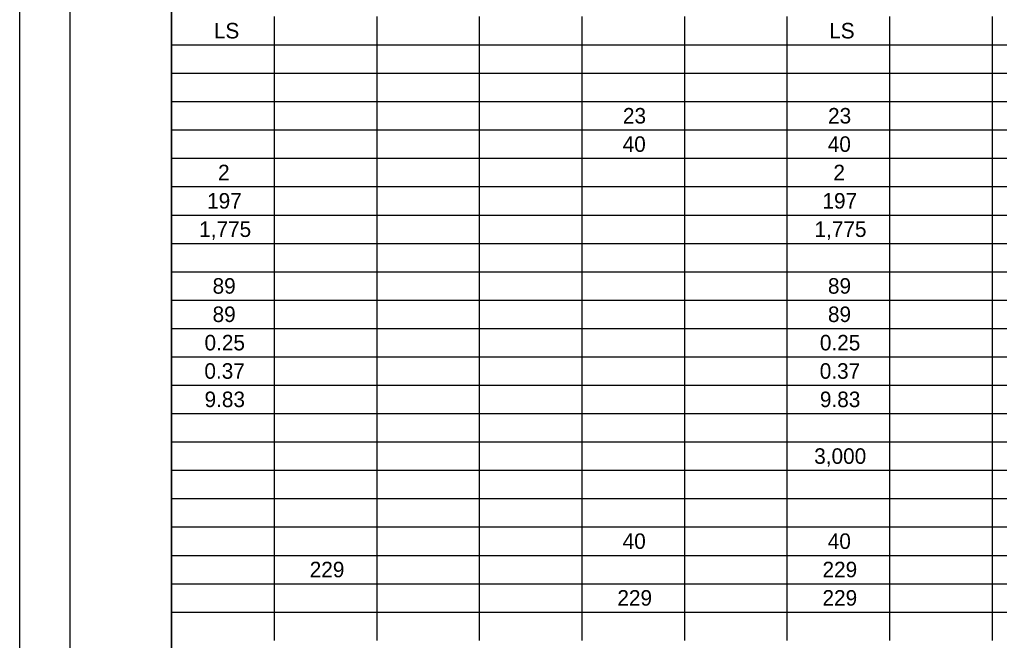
# Model space of a CAD drawing. Extents: x 0 to 34, y 0 to 22.
# Drawn here: x 0 to 9.67, y 9.74 to 15.87 of the extents above; entities that cross this region are included whole.
import ezdxf

# ---------------------------------------------------------------- set-up
doc = ezdxf.new("R2010")
doc.units = 0
for name, color, linetype in [('SH_Border', 7, 'Continuous'), ('SH_Cut_Line', 7, 'Continuous'), ('SH_Text', 7, 'Continuous')]:
    doc.layers.add(name, color=color, linetype=linetype)

msp = doc.modelspace()

# ---------------------------------------------------------------- linework, layer by layer
at = {"layer": 'SH_Border'}
for points in [[(0.5, 21.5), (1.5, 21.5), (1.5, 0.5), (0.5, 0.5)], [(1.5, 21.5), (33.5, 21.5), (33.5, 0.5), (1.5, 0.5)]]:
    msp.add_lwpolyline(points, close=True, dxfattribs=at)
at = {"layer": 'SH_Cut_Line'}
msp.add_lwpolyline([(0, 0), (34, 0), (34, 22), (0, 22)], close=True, dxfattribs=at)
at = {"layer": 'SH_Text'}
for p, q in [((1.5, 15.9), (1.5, 15.62)), ((2.5119, 15.9), (2.5119, 15.62)), ((3.5238, 15.9), (3.5238, 15.62)), ((4.5357, 15.9), (4.5357, 15.62)), ((5.5476, 15.9), (5.5476, 15.62)), ((6.5595, 15.9), (6.5595, 15.62)), ((7.5715, 15.9), (7.5715, 15.62)), ((8.5834, 15.9), (8.5834, 15.62)), ((9.5953, 15.9), (9.5953, 15.62)), ((1.5, 15.62), (6.5595, 15.62)), ((1.5, 15.62), (1.5, 15.34)), ((2.5119, 15.62), (2.5119, 15.34)), ((3.5238, 15.62), (3.5238, 15.34)), ((4.5357, 15.62), (4.5357, 15.34)), ((5.5476, 15.62), (5.5476, 15.34)), ((6.5595, 15.62), (7.5715, 15.62)), ((6.5595, 15.62), (6.5595, 15.34)), ((7.5715, 15.62), (13.3316, 15.62)), ((7.5715, 15.62), (7.5715, 15.34)), ((8.5834, 15.62), (8.5834, 15.34)), ((9.5953, 15.62), (9.5953, 15.34)), ((1.5, 15.34), (6.5595, 15.34)), ((1.5, 15.34), (1.5, 14.78)), ((2.5119, 15.34), (2.5119, 14.78)), ((3.5238, 15.34), (3.5238, 14.78)), ((4.5357, 15.34), (4.5357, 14.78)), ((5.5476, 15.34), (5.5476, 14.78)), ((6.5595, 15.34), (7.5715, 15.34)), ((6.5595, 15.34), (6.5595, 14.78)), ((7.5715, 15.34), (13.3316, 15.34)), ((7.5715, 15.34), (7.5715, 14.78)), ((8.5834, 15.34), (8.5834, 14.78)), ((9.5953, 15.34), (9.5953, 14.78)), ((1.5, 15.06), (6.5595, 15.06)), ((6.5595, 15.06), (7.5715, 15.06)), ((7.5715, 15.06), (13.3316, 15.06)), ((1.5, 14.78), (6.5595, 14.78)), ((1.5, 14.78), (1.5, 14.5)), ((2.5119, 14.78), (2.5119, 14.5)), ((3.5238, 14.78), (3.5238, 14.5)), ((4.5357, 14.78), (4.5357, 14.5)), ((5.5476, 14.78), (5.5476, 14.5)), ((6.5595, 14.78), (7.5715, 14.78)), ((6.5595, 14.78), (6.5595, 14.5)), ((7.5715, 14.78), (13.3316, 14.78)), ((7.5715, 14.78), (7.5715, 14.5)), ((8.5834, 14.78), (8.5834, 14.5)), ((9.5953, 14.78), (9.5953, 14.5)), ((1.5, 14.5), (6.5595, 14.5)), ((1.5, 14.5), (1.5, 14.22)), ((2.5119, 14.5), (2.5119, 14.22)), ((3.5238, 14.5), (3.5238, 14.22)), ((4.5357, 14.5), (4.5357, 14.22)), ((5.5476, 14.5), (5.5476, 14.22)), ((6.5595, 14.5), (7.5715, 14.5)), ((6.5595, 14.5), (6.5595, 14.22)), ((7.5715, 14.5), (13.3316, 14.5)), ((7.5715, 14.5), (7.5715, 14.22)), ((8.5834, 14.5), (8.5834, 14.22)), ((9.5953, 14.5), (9.5953, 14.22)), ((1.5, 14.22), (6.5595, 14.22)), ((1.5, 14.22), (1.5, 13.94)), ((2.5119, 14.22), (2.5119, 13.94)), ((3.5238, 14.22), (3.5238, 13.94)), ((4.5357, 14.22), (4.5357, 13.94)), ((5.5476, 14.22), (5.5476, 13.94)), ((6.5595, 14.22), (7.5715, 14.22)), ((6.5595, 14.22), (6.5595, 13.94)), ((7.5715, 14.22), (13.3316, 14.22)), ((7.5715, 14.22), (7.5715, 13.94)), ((8.5834, 14.22), (8.5834, 13.94)), ((9.5953, 14.22), (9.5953, 13.94)), ((1.5, 13.94), (6.5595, 13.94)), ((1.5, 13.94), (1.5, 11.7)), ((2.5119, 13.94), (2.5119, 11.7)), ((3.5238, 13.94), (3.5238, 11.7)), ((4.5357, 13.94), (4.5357, 11.7)), ((5.5476, 13.94), (5.5476, 11.7)), ((6.5595, 13.94), (7.5715, 13.94)), ((6.5595, 13.94), (6.5595, 11.7)), ((7.5715, 13.94), (13.3316, 13.94)), ((7.5715, 13.94), (7.5715, 11.7)), ((8.5834, 13.94), (8.5834, 11.7)), ((9.5953, 13.94), (9.5953, 11.7)), ((1.5, 13.66), (6.5595, 13.66)), ((6.5595, 13.66), (7.5715, 13.66)), ((7.5715, 13.66), (13.3316, 13.66)), ((1.5, 13.38), (6.5595, 13.38)), ((6.5595, 13.38), (7.5715, 13.38)), ((7.5715, 13.38), (13.3316, 13.38)), ((1.5, 13.1), (6.5595, 13.1)), ((6.5595, 13.1), (7.5715, 13.1)), ((7.5715, 13.1), (13.3316, 13.1)), ((1.5, 12.82), (6.5595, 12.82)), ((6.5595, 12.82), (7.5715, 12.82)), ((7.5715, 12.82), (13.3316, 12.82)), ((1.5, 12.54), (6.5595, 12.54)), ((6.5595, 12.54), (7.5715, 12.54)), ((7.5715, 12.54), (13.3316, 12.54)), ((1.5, 12.26), (6.5595, 12.26)), ((6.5595, 12.26), (7.5715, 12.26)), ((7.5715, 12.26), (13.3316, 12.26)), ((1.5, 11.98), (6.5595, 11.98)), ((6.5595, 11.98), (7.5715, 11.98)), ((7.5715, 11.98), (13.3316, 11.98)), ((1.5, 11.7), (6.5595, 11.7)), ((1.5, 11.7), (1.5, 11.42)), ((2.5119, 11.7), (2.5119, 11.42)), ((3.5238, 11.7), (3.5238, 11.42)), ((4.5357, 11.7), (4.5357, 11.42)), ((5.5476, 11.7), (5.5476, 11.42)), ((6.5595, 11.7), (7.5715, 11.7)), ((6.5595, 11.7), (6.5595, 11.42)), ((7.5715, 11.7), (13.3316, 11.7)), ((7.5715, 11.7), (7.5715, 11.42)), ((8.5834, 11.7), (8.5834, 11.42)), ((9.5953, 11.7), (9.5953, 11.42)), ((1.5, 11.42), (6.5595, 11.42)), ((1.5, 11.42), (1.5, 10.3)), ((2.5119, 11.42), (2.5119, 10.3)), ((3.5238, 11.42), (3.5238, 10.3)), ((4.5357, 11.42), (4.5357, 10.3)), ((5.5476, 11.42), (5.5476, 10.3)), ((6.5595, 11.42), (7.5715, 11.42)), ((6.5595, 11.42), (6.5595, 10.3)), ((7.5715, 11.42), (13.3316, 11.42)), ((7.5715, 11.42), (7.5715, 10.3)), ((8.5834, 11.42), (8.5834, 10.3)), ((9.5953, 11.42), (9.5953, 10.3)), ((1.5, 11.14), (6.5595, 11.14)), ((6.5595, 11.14), (7.5715, 11.14)), ((7.5715, 11.14), (13.3316, 11.14)), ((1.5, 10.86), (6.5595, 10.86)), ((6.5595, 10.86), (7.5715, 10.86)), ((7.5715, 10.86), (13.3316, 10.86)), ((1.5, 10.58), (6.5595, 10.58)), ((6.5595, 10.58), (7.5715, 10.58)), ((7.5715, 10.58), (13.3316, 10.58)), ((1.5, 10.3), (6.5595, 10.3)), ((1.5, 10.3), (1.5, 10.02)), ((2.5119, 10.3), (2.5119, 10.02)), ((3.5238, 10.3), (3.5238, 10.02)), ((4.5357, 10.3), (4.5357, 10.02)), ((5.5476, 10.3), (5.5476, 10.02)), ((6.5595, 10.3), (7.5715, 10.3)), ((6.5595, 10.3), (6.5595, 10.02)), ((7.5715, 10.3), (13.3316, 10.3)), ((7.5715, 10.3), (7.5715, 10.02)), ((8.5834, 10.3), (8.5834, 10.02)), ((9.5953, 10.3), (9.5953, 10.02)), ((1.5, 10.02), (6.5595, 10.02)), ((1.5, 10.02), (1.5, 9.74)), ((2.5119, 10.02), (2.5119, 9.74)), ((3.5238, 10.02), (3.5238, 9.74)), ((4.5357, 10.02), (4.5357, 9.74)), ((5.5476, 10.02), (5.5476, 9.74)), ((6.5595, 10.02), (7.5715, 10.02)), ((6.5595, 10.02), (6.5595, 9.74)), ((7.5715, 10.02), (13.3316, 10.02)), ((7.5715, 10.02), (7.5715, 9.74)), ((8.5834, 10.02), (8.5834, 9.74)), ((9.5953, 10.02), (9.5953, 9.74))]:
    msp.add_line(p, q, dxfattribs=at)

# ---------------------------------------------------------------- texts
for s, height, p in [('LS', 0.15333, (1.9168, 15.6833)), ('LS', 0.15333, (7.9882, 15.6833)), ('23', 0.15333, (5.9529, 14.8433)), ('23', 0.15333, (7.9767, 14.8433)), ('40', 0.15333, (5.9501, 14.5633)), ('40', 0.15333, (7.9739, 14.5633)), ('2', 0.1533, (1.9582, 14.2833)), ('2', 0.1533, (8.0297, 14.2833)), ('197', 0.15333, (1.8501, 14.0033)), ('197', 0.15333, (7.9215, 14.0033)), ('1,775', 0.15333, (1.7714, 13.7233)), ('1,775', 0.15333, (7.8428, 13.7233)), ('89', 0.15333, (1.9041, 13.1633)), ('89', 0.15333, (7.9756, 13.1633)), ('89', 0.15333, (1.9041, 12.8833)), ('89', 0.15333, (7.9756, 12.8833)), ('0.25', 0.15333, (1.8247, 12.6033)), ('0.25', 0.15333, (7.8961, 12.6033)), ('0.37', 0.15333, (1.8233, 12.3233)), ('0.37', 0.15333, (7.8948, 12.3233)), ('9.83', 0.15333, (1.8249, 12.0433)), ('9.83', 0.15333, (7.8964, 12.0433)), ('3,000', 0.15333, (7.8403, 11.4833)), ('40', 0.15333, (5.9501, 10.6433)), ('40', 0.15333, (7.9739, 10.6433)), ('229', 0.15333, (2.8625, 10.3633)), ('229', 0.15333, (7.922, 10.3633)), ('229', 0.15333, (5.8982, 10.0833)), ('229', 0.15333, (7.922, 10.0833))]:
    msp.add_text(s, height=height, dxfattribs=at).set_placement(p)

doc.saveas('drawing.dxf')
